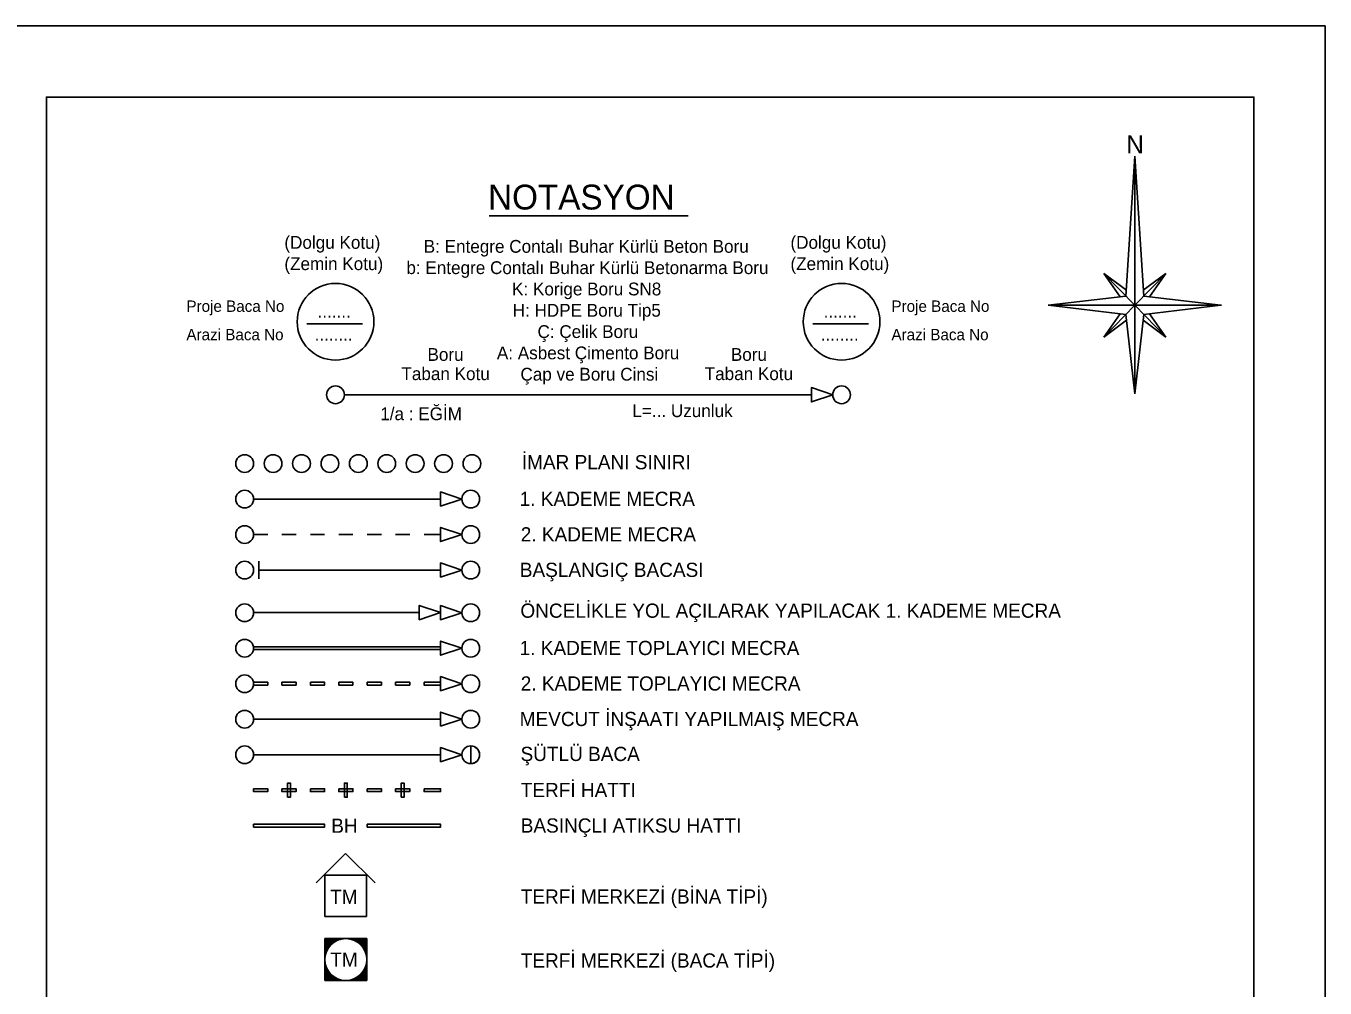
# Model space of a CAD drawing. Extents: x -10 to 1145, y -10 to 821.
# Drawn here: x 962.1 to 1145, y 685.6 to 821 of the extents above; entities that cross this region are included whole.
import ezdxf

# ---------------------------------------------------------------- set-up
doc = ezdxf.new("R2010")
doc.units = 0
for name, color, linetype in [('Default', 7, 'Continuous'), ('Lejand', 7, 'Continuous'), ('Level 51', 7, 'Continuous'), ('Level 52', 7, 'Continuous')]:
    doc.layers.add(name, color=color, linetype=linetype)

# ---------------------------------------------------------------- blocks, each defined once
blk = doc.blocks.new('OK')
at = {"layer": 'Default'}
blk.add_lwpolyline([(1.25, 0), (4.25, 1), (4.25, -1), (1.25, 0)], dxfattribs=at)
blk = doc.blocks.new('MENHOLE')
at = {"layer": 'Default'}
blk.add_circle((0, 0), 1.25, dxfattribs=at)

msp = doc.modelspace()

# ---------------------------------------------------------------- linework, layer by layer
at = {"layer": 'Lejand'}
for p, q in [((1118.22, 802.67), (1116.97, 782.96)), ((1118.22, 802.67), (1119.47, 782.96)), ((1118.22, 802.67), (1118.22, 769.23)), ((1027.33, 794.26), (1055.35, 794.26)), ((1113.84, 786.17), (1117.03, 783.81)), ((1116.17, 782.87), (1113.84, 786.17)), ((1113.84, 786.17), (1118.22, 781.68)), ((1122.6, 786.17), (1118.22, 781.68)), ((1122.6, 786.17), (1119.42, 783.81)), ((1120.27, 782.87), (1122.6, 786.17)), ((1106.03, 781.68), (1116.97, 782.96)), ((1130.35, 781.68), (1119.47, 782.96)), ((1118.22, 781.68), (1106.03, 781.68)), ((1106.03, 781.68), (1116.97, 780.4)), ((1113.84, 777.19), (1118.22, 781.68)), ((1122.6, 777.19), (1118.22, 781.68)), ((1118.22, 781.68), (1130.41, 781.68)), ((1130.35, 781.68), (1119.47, 780.4)), ((1116.17, 780.49), (1113.84, 777.19)), ((1113.84, 777.19), (1117.07, 779.58)), ((1116.97, 780.4), (1118.22, 769.23)), ((1119.47, 780.4), (1118.22, 769.23)), ((1122.6, 777.19), (1119.38, 779.58)), ((1120.27, 780.49), (1122.6, 777.19)), ((1001.65, 779.07), (1009.48, 779.07)), ((1072.9, 779.07), (1080.74, 779.07)), ((1006.94, 769.07), (1072.69, 769.08)), ((1020.48, 754.4), (994.15, 754.4)), ((996.15, 749.4), (994.15, 749.4)), ((1000.15, 749.4), (998.15, 749.4)), ((1004.15, 749.4), (1002.15, 749.4)), ((1008.15, 749.4), (1006.15, 749.4)), ((1012.15, 749.4), (1010.15, 749.4)), ((1016.15, 749.4), (1014.15, 749.4)), ((1020.48, 749.4), (1018.15, 749.4)), ((994.9, 745.64), (994.9, 743.14)), ((1020.48, 744.4), (994.9, 744.4)), ((1017.48, 738.41), (994.15, 738.41)), ((1020.48, 723.4), (994.15, 723.4)), ((1020.48, 718.4), (994.15, 718.4)), ((1007.12, 704.5), (1002.98, 700.37)), ((1007.12, 704.5), (1011.25, 700.37)), ((1010.04, 701.45), (1004.19, 701.45)), ((1004.19, 701.45), (1004.19, 695.6)), ((1010.04, 701.45), (1010.04, 695.6)), ((1010.04, 695.6), (1004.19, 695.6)), ((1004.19, 692.5), (1004.19, 686.6)), ((1010.09, 692.5), (1004.19, 692.5)), ((1006.38, 692.4), (1004.19, 692.4)), ((1006.07, 692.3), (1004.19, 692.3)), ((1005.85, 692.2), (1004.19, 692.2)), ((1005.66, 692.1), (1004.19, 692.1)), ((1005.5, 692), (1004.19, 692)), ((1005.36, 691.9), (1004.19, 691.9)), ((1005.23, 691.8), (1004.19, 691.8)), ((1005.12, 691.7), (1004.19, 691.7)), ((1005.02, 691.6), (1004.19, 691.6)), ((1004.93, 691.5), (1004.19, 691.5)), ((1004.84, 691.4), (1004.19, 691.4)), ((1004.29, 692.5), (1004.29, 690.31)), ((1004.39, 692.5), (1004.39, 690.62)), ((1004.49, 692.5), (1004.49, 690.85)), ((1004.59, 692.5), (1004.59, 691.03)), ((1004.69, 692.5), (1004.69, 691.19)), ((1004.79, 692.5), (1004.79, 691.33)), ((1004.89, 692.5), (1004.89, 691.46)), ((1004.99, 692.5), (1004.99, 691.57)), ((1005.09, 692.5), (1005.09, 691.67)), ((1005.19, 692.5), (1005.19, 691.76)), ((1005.29, 692.5), (1005.29, 691.85)), ((1005.39, 692.5), (1005.39, 691.93)), ((1005.49, 692.5), (1005.49, 692)), ((1005.59, 692.5), (1005.59, 692.06)), ((1005.69, 692.5), (1005.69, 692.12)), ((1005.79, 692.5), (1005.79, 692.17)), ((1005.89, 692.5), (1005.89, 692.22)), ((1005.99, 692.5), (1005.99, 692.27)), ((1006.09, 692.5), (1006.09, 692.31)), ((1006.19, 692.5), (1006.19, 692.34)), ((1006.29, 692.5), (1006.29, 692.38)), ((1006.39, 692.5), (1006.39, 692.4)), ((1006.49, 692.5), (1006.49, 692.43)), ((1006.59, 692.5), (1006.59, 692.45)), ((1006.69, 692.5), (1006.69, 692.47)), ((1006.79, 692.5), (1006.79, 692.48)), ((1007.39, 692.5), (1007.39, 692.49)), ((1007.49, 692.5), (1007.49, 692.48)), ((1007.59, 692.5), (1007.59, 692.47)), ((1007.69, 692.5), (1007.69, 692.45)), ((1007.79, 692.5), (1007.79, 692.43)), ((1007.89, 692.5), (1007.89, 692.4)), ((1010.09, 692.4), (1007.9, 692.4)), ((1007.99, 692.5), (1007.99, 692.38)), ((1008.09, 692.5), (1008.09, 692.34)), ((1008.19, 692.5), (1008.19, 692.31)), ((1010.09, 692.3), (1008.21, 692.3)), ((1008.29, 692.5), (1008.29, 692.27)), ((1008.39, 692.5), (1008.39, 692.22)), ((1010.09, 692.2), (1008.44, 692.2)), ((1008.49, 692.5), (1008.49, 692.17)), ((1008.59, 692.5), (1008.59, 692.12)), ((1010.09, 692.1), (1008.63, 692.1)), ((1008.69, 692.5), (1008.69, 692.06)), ((1008.79, 692.5), (1008.79, 692)), ((1010.09, 692), (1008.79, 692)), ((1008.89, 692.5), (1008.89, 691.93)), ((1010.09, 691.9), (1008.93, 691.9)), ((1008.99, 692.5), (1008.99, 691.85)), ((1010.09, 691.8), (1009.05, 691.8)), ((1009.09, 692.5), (1009.09, 691.76)), ((1010.09, 691.7), (1009.16, 691.7)), ((1009.19, 692.5), (1009.19, 691.67)), ((1010.09, 691.6), (1009.26, 691.6)), ((1009.29, 692.5), (1009.29, 691.57)), ((1010.09, 691.5), (1009.36, 691.5)), ((1009.39, 692.5), (1009.39, 691.46)), ((1010.09, 691.4), (1009.44, 691.4)), ((1009.49, 692.5), (1009.49, 691.33)), ((1009.59, 692.5), (1009.59, 691.19)), ((1009.69, 692.5), (1009.69, 691.03)), ((1009.79, 692.5), (1009.79, 690.85)), ((1009.89, 692.5), (1009.89, 690.62)), ((1009.99, 692.5), (1009.99, 690.31)), ((1010.09, 692.5), (1010.09, 686.6)), ((1004.77, 691.3), (1004.19, 691.3)), ((1004.7, 691.2), (1004.19, 691.2)), ((1004.63, 691.1), (1004.19, 691.1)), ((1004.57, 691), (1004.19, 691)), ((1004.52, 690.9), (1004.19, 690.9)), ((1004.47, 690.8), (1004.19, 690.8)), ((1004.43, 690.7), (1004.19, 690.7)), ((1004.39, 690.6), (1004.19, 690.6)), ((1004.35, 690.5), (1004.19, 690.5)), ((1004.32, 690.4), (1004.19, 690.4)), ((1004.29, 690.3), (1004.19, 690.3)), ((1004.26, 690.2), (1004.19, 690.2)), ((1004.24, 690.1), (1004.19, 690.1)), ((1004.23, 690), (1004.19, 690)), ((1004.21, 689.9), (1004.19, 689.9)), ((1004.2, 689.8), (1004.19, 689.8)), ((1010.09, 691.3), (1009.52, 691.3)), ((1010.09, 691.2), (1009.59, 691.2)), ((1010.09, 691.1), (1009.65, 691.1)), ((1010.09, 691), (1009.71, 691)), ((1010.09, 690.9), (1009.77, 690.9)), ((1010.09, 690.8), (1009.81, 690.8)), ((1010.09, 690.7), (1009.86, 690.7)), ((1010.09, 690.6), (1009.9, 690.6)), ((1010.09, 690.5), (1009.94, 690.5)), ((1010.09, 690.4), (1009.97, 690.4)), ((1010.09, 690.3), (1010, 690.3)), ((1010.09, 690.2), (1010.02, 690.2)), ((1010.09, 690.1), (1010.04, 690.1)), ((1010.09, 690), (1010.06, 690)), ((1010.09, 689.9), (1010.07, 689.9)), ((1004.2, 689.4), (1004.19, 689.4)), ((1004.21, 689.2), (1004.19, 689.2)), ((1004.23, 689.1), (1004.19, 689.1)), ((1004.24, 689), (1004.19, 689)), ((1004.26, 688.9), (1004.19, 688.9)), ((1004.29, 688.8), (1004.19, 688.8)), ((1004.32, 688.7), (1004.19, 688.7)), ((1004.35, 688.6), (1004.19, 688.6)), ((1004.39, 688.5), (1004.19, 688.5)), ((1004.43, 688.4), (1004.19, 688.4)), ((1004.47, 688.3), (1004.19, 688.3)), ((1004.52, 688.2), (1004.19, 688.2)), ((1004.57, 688.1), (1004.19, 688.1)), ((1004.63, 688), (1004.19, 688)), ((1004.7, 687.9), (1004.19, 687.9)), ((1004.77, 687.8), (1004.19, 687.8)), ((1004.84, 687.7), (1004.19, 687.7)), ((1004.29, 688.79), (1004.29, 686.6)), ((1004.39, 688.48), (1004.39, 686.6)), ((1004.49, 688.25), (1004.49, 686.6)), ((1004.59, 688.07), (1004.59, 686.6)), ((1004.69, 687.91), (1004.69, 686.6)), ((1004.79, 687.77), (1004.79, 686.6)), ((1010.09, 687.7), (1009.44, 687.7)), ((1009.49, 687.77), (1009.49, 686.6)), ((1010.09, 687.8), (1009.52, 687.8)), ((1009.59, 687.91), (1009.59, 686.6)), ((1010.09, 687.9), (1009.59, 687.9)), ((1010.09, 688), (1009.65, 688)), ((1009.69, 688.07), (1009.69, 686.6)), ((1010.09, 688.1), (1009.71, 688.1)), ((1010.09, 688.2), (1009.77, 688.2)), ((1009.79, 688.25), (1009.79, 686.6)), ((1010.09, 688.3), (1009.81, 688.3)), ((1010.09, 688.4), (1009.86, 688.4)), ((1009.89, 688.48), (1009.89, 686.6)), ((1010.09, 688.5), (1009.9, 688.5)), ((1010.09, 688.6), (1009.94, 688.6)), ((1010.09, 688.7), (1009.97, 688.7)), ((1009.99, 688.79), (1009.99, 686.6)), ((1010.09, 688.8), (1010, 688.8)), ((1010.09, 688.9), (1010.02, 688.9)), ((1010.09, 689), (1010.04, 689)), ((1010.09, 689.1), (1010.06, 689.1)), ((1010.09, 689.2), (1010.07, 689.2)), ((1010.09, 689.3), (1010.08, 689.3)), ((1004.93, 687.6), (1004.19, 687.6)), ((1005.02, 687.5), (1004.19, 687.5)), ((1005.12, 687.4), (1004.19, 687.4)), ((1005.23, 687.3), (1004.19, 687.3)), ((1005.36, 687.2), (1004.19, 687.2)), ((1005.5, 687.1), (1004.19, 687.1)), ((1005.66, 687), (1004.19, 687)), ((1005.85, 686.9), (1004.19, 686.9)), ((1006.07, 686.8), (1004.19, 686.8)), ((1006.38, 686.7), (1004.19, 686.7)), ((1010.09, 686.6), (1004.19, 686.6)), ((1004.89, 687.64), (1004.89, 686.6)), ((1004.99, 687.53), (1004.99, 686.6)), ((1005.09, 687.43), (1005.09, 686.6)), ((1005.19, 687.34), (1005.19, 686.6)), ((1005.29, 687.25), (1005.29, 686.6)), ((1005.39, 687.18), (1005.39, 686.6)), ((1005.49, 687.1), (1005.49, 686.6)), ((1005.59, 687.04), (1005.59, 686.6)), ((1005.69, 686.98), (1005.69, 686.6)), ((1005.79, 686.93), (1005.79, 686.6)), ((1005.89, 686.88), (1005.89, 686.6)), ((1005.99, 686.83), (1005.99, 686.6)), ((1006.09, 686.79), (1006.09, 686.6)), ((1006.19, 686.76), (1006.19, 686.6)), ((1006.29, 686.73), (1006.29, 686.6)), ((1006.39, 686.7), (1006.39, 686.6)), ((1006.49, 686.67), (1006.49, 686.6)), ((1006.59, 686.65), (1006.59, 686.6)), ((1006.69, 686.63), (1006.69, 686.6)), ((1006.79, 686.62), (1006.79, 686.6)), ((1007.49, 686.62), (1007.49, 686.6)), ((1007.59, 686.63), (1007.59, 686.6)), ((1007.69, 686.65), (1007.69, 686.6)), ((1007.79, 686.67), (1007.79, 686.6)), ((1007.89, 686.7), (1007.89, 686.6)), ((1010.09, 686.7), (1007.9, 686.7)), ((1007.99, 686.73), (1007.99, 686.6)), ((1008.09, 686.76), (1008.09, 686.6)), ((1008.19, 686.79), (1008.19, 686.6)), ((1010.09, 686.8), (1008.21, 686.8)), ((1008.29, 686.83), (1008.29, 686.6)), ((1008.39, 686.88), (1008.39, 686.6)), ((1010.09, 686.9), (1008.44, 686.9)), ((1008.49, 686.93), (1008.49, 686.6)), ((1008.59, 686.98), (1008.59, 686.6)), ((1010.09, 687), (1008.63, 687)), ((1008.69, 687.04), (1008.69, 686.6)), ((1008.79, 687.1), (1008.79, 686.6)), ((1010.09, 687.1), (1008.79, 687.1)), ((1008.89, 687.18), (1008.89, 686.6)), ((1010.09, 687.2), (1008.93, 687.2)), ((1008.99, 687.25), (1008.99, 686.6)), ((1010.09, 687.3), (1009.05, 687.3)), ((1009.09, 687.34), (1009.09, 686.6)), ((1010.09, 687.4), (1009.16, 687.4)), ((1009.19, 687.43), (1009.19, 686.6)), ((1010.09, 687.5), (1009.26, 687.5)), ((1009.29, 687.53), (1009.29, 686.6)), ((1010.09, 687.6), (1009.36, 687.6)), ((1009.39, 687.64), (1009.39, 686.6))]:
    msp.add_line(p, q, dxfattribs=at)
for points in [[(994.15, 733.6), (1020.48, 733.6), (1020.48, 733.2), (994.15, 733.2)], [(994.15, 728.6), (996.15, 728.6), (996.15, 728.2), (994.15, 728.2)], [(998.15, 728.6), (1000.15, 728.6), (1000.15, 728.2), (998.15, 728.2)], [(1002.15, 728.6), (1004.15, 728.6), (1004.15, 728.2), (1002.15, 728.2)], [(1006.15, 728.6), (1008.15, 728.6), (1008.15, 728.2), (1006.15, 728.2)], [(1010.15, 728.6), (1012.15, 728.6), (1012.15, 728.2), (1010.15, 728.2)], [(1014.15, 728.6), (1016.15, 728.6), (1016.15, 728.2), (1014.15, 728.2)], [(1018.15, 728.6), (1020.48, 728.6), (1020.48, 728.2), (1018.15, 728.2)], [(1020.47, 722.4), (1020.48, 724.4), (1023.48, 723.39)], [(994.15, 713.6), (996.15, 713.6), (996.15, 713.2), (994.15, 713.2)], [(998.15, 713.6), (1000.15, 713.6), (1000.15, 713.2), (998.15, 713.2)], [(998.95, 712.4), (998.95, 714.4), (999.35, 714.4), (999.35, 712.4)], [(1002.15, 713.6), (1004.15, 713.6), (1004.15, 713.2), (1002.15, 713.2)], [(1006.15, 713.6), (1008.15, 713.6), (1008.15, 713.2), (1006.15, 713.2)], [(1006.95, 712.4), (1006.95, 714.4), (1007.35, 714.4), (1007.35, 712.4)], [(1010.15, 713.6), (1012.15, 713.6), (1012.15, 713.2), (1010.15, 713.2)], [(1014.15, 713.6), (1016.15, 713.6), (1016.15, 713.2), (1014.15, 713.2)], [(1014.95, 712.4), (1014.95, 714.4), (1015.35, 714.4), (1015.35, 712.4)], [(1018.15, 713.6), (1020.48, 713.6), (1020.48, 713.2), (1018.15, 713.2)], [(994.15, 708.6), (1004.15, 708.6), (1004.15, 708.2), (994.15, 708.2)], [(1010.15, 708.6), (1020.48, 708.6), (1020.48, 708.2), (1010.15, 708.2)]]:
    msp.add_lwpolyline(points, close=True, dxfattribs=at)
msp.add_lwpolyline([(1024.73, 717.14), (1024.97, 717.16), (1025.21, 717.23), (1025.42, 717.35), (1025.61, 717.51), (1025.77, 717.7), (1025.88, 717.91), (1025.95, 718.15), (1025.98, 718.39), (1025.95, 718.63), (1025.88, 718.87), (1025.77, 719.08), (1025.61, 719.27), (1025.42, 719.43), (1025.21, 719.54), (1024.97, 719.62), (1024.73, 719.64), (1024.73, 717.14)], dxfattribs=at)
for centre, radius in [((1005.69, 779.36), 5.4), ((1076.94, 779.36), 5.4), ((992.9, 759.39), 1.25), ((996.9, 759.39), 1.25), ((1000.9, 759.39), 1.25), ((1004.9, 759.39), 1.25), ((1008.9, 759.39), 1.25), ((1012.9, 759.39), 1.25), ((1016.9, 759.39), 1.25), ((1020.9, 759.39), 1.25), ((1024.9, 759.39), 1.25), ((992.9, 723.39), 1.25), ((1024.73, 723.39), 1.25), ((1007.14, 689.55), 2.95)]:
    msp.add_circle(centre, radius, dxfattribs=at)
at = {"layer": 'Level 51'}
msp.add_lwpolyline([(-10, -10), (1145, -10), (1145, 821), (-10, 821)], close=True, dxfattribs=at)
at = {"layer": 'Level 52'}
msp.add_lwpolyline([(965, 287), (1135, 287), (1135, 811), (965, 811)], close=True, dxfattribs=at)

# ---------------------------------------------------------------- block references
at = {"layer": 'Lejand'}
for name, p, xscale, yscale, rotation in [('MENHOLE', (1005.69, 769.07), 1.0000122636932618, 1.0000122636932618, 0.0008205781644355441), ('OK', (1076.94, 769.07), 1.000012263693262, 1.0000122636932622, 179.87420678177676), ('MENHOLE', (1076.94, 769.07), 1.0000122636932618, 1.0000122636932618, 0.0008205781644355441), ('MENHOLE', (992.9, 754.39), 1.0000122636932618, 1.0000122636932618, 0.0008205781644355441), ('OK', (1024.73, 754.39), 1.000012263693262, 1.0000122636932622, 179.87420678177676), ('MENHOLE', (1024.73, 754.39), 1.0000122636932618, 1.0000122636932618, 0.0008205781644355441), ('MENHOLE', (992.9, 749.39), 1.0000122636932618, 1.0000122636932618, 0.0008205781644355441), ('OK', (1024.73, 749.39), 1.000012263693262, 1.0000122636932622, 179.87420678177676), ('MENHOLE', (1024.73, 749.39), 1.0000122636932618, 1.0000122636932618, 0.0008205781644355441), ('MENHOLE', (992.9, 744.39), 1.0000122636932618, 1.0000122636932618, 0.0008205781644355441), ('OK', (1024.73, 744.39), 1.000012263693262, 1.0000122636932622, 179.87420678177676), ('MENHOLE', (1024.73, 744.39), 1.0000122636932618, 1.0000122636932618, 0.0008205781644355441), ('MENHOLE', (992.9, 738.39), 1.0000122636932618, 1.0000122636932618, 0.0008205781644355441), ('OK', (1021.73, 738.4), 1.000012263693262, 1.0000122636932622, 179.87420678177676), ('OK', (1024.73, 738.39), 1.000012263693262, 1.0000122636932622, 179.87420678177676), ('MENHOLE', (1024.73, 738.39), 1.0000122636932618, 1.0000122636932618, 0.0008205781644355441), ('MENHOLE', (992.9, 733.39), 1.0000122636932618, 1.0000122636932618, 0.0008205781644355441), ('OK', (1024.73, 733.39), 1.000012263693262, 1.0000122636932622, 179.87420678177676), ('MENHOLE', (1024.73, 733.39), 1.0000122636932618, 1.0000122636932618, 0.0008205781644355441), ('MENHOLE', (992.9, 728.39), 1.0000122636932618, 1.0000122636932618, 0.0008205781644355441), ('OK', (1024.73, 728.39), 1.000012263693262, 1.0000122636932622, 179.87420678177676), ('MENHOLE', (1024.73, 728.39), 1.0000122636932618, 1.0000122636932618, 0.0008205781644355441), ('MENHOLE', (992.9, 718.39), 1.0000122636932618, 1.0000122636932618, 0.0008205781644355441), ('OK', (1024.73, 718.39), 1.000012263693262, 1.0000122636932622, 179.87420678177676), ('MENHOLE', (1024.73, 718.39), 1.0000122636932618, 1.0000122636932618, 0.0008205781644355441)]:
    msp.add_blockref(name, p, dxfattribs=dict(at, xscale=xscale, yscale=yscale, rotation=rotation))

# ---------------------------------------------------------------- texts
msp.add_text('N', height=2.56, dxfattribs=at).set_placement((1117.02, 803.06))
for s, height, p in [('NOTASYON', 3.5, (1027.17, 795.16)), ('(Dolgu Kotu)', 1.8, (998.49, 789.63)), ('B: Entegre Contalı Buhar Kürlü Beton Boru', 1.8, (1018.11, 789.07)), ('(Dolgu Kotu)', 1.8, (1069.74, 789.63)), ('(Zemin Kotu)', 1.8, (998.49, 786.63)), ('(Zemin Kotu)', 1.8, (1069.74, 786.63)), ('b: Entegre Contalı Buhar Kürlü Betonarma Boru', 1.8, (1015.67, 786.07)), ('K: Korige Boru SN8', 1.8, (1030.55, 783.07)), ('Proje Baca No', 1.6, (984.7, 780.75)), ('H: HDPE Boru Tip5', 1.8, (1030.63, 780.07)), ('Proje Baca No', 1.6, (1083.96, 780.75)), ('.......', 1.8, (1003.16, 779.94)), ('.......', 1.8, (1074.41, 779.94)), ('Arazi Baca No', 1.6, (984.7, 776.75)), ('Ç: Çelik Boru', 1.8, (1034.13, 777.07)), ('Arazi Baca No', 1.6, (1083.96, 776.75)), ('........', 1.8, (1002.75, 776.7)), ('Boru', 1.8, (1018.64, 773.85)), ('A: Asbest Çimento Boru', 1.8, (1028.41, 774.07)), ('Boru', 1.8, (1061.35, 773.85)), ('........', 1.8, (1074, 776.7)), ('Taban Kotu', 1.8, (1014.97, 771.14)), ('Çap ve Boru Cinsi', 1.8, (1031.73, 771.07)), ('Taban Kotu', 1.8, (1057.67, 771.14)), ('1/a : EĞİM', 1.8, (1011.99, 765.5)), ('L=... Uzunluk', 1.8, (1047.49, 765.93)), ('İMAR PLANI SINIRI', 2, (1031.92, 758.59)), ('1. KADEME MECRA', 2, (1031.62, 753.43)), ('2. KADEME MECRA', 2, (1031.77, 748.43)), ('BAŞLANGIÇ BACASI', 2, (1031.64, 743.43)), ('ÖNCELİKLE YOL AÇILARAK YAPILACAK 1. KADEME MECRA', 2, (1031.72, 737.68)), ('1. KADEME TOPLAYICI MECRA', 2, (1031.62, 732.43)), ('2. KADEME TOPLAYICI MECRA', 2, (1031.77, 727.43)), ('MEVCUT İNŞAATI YAPILMAIŞ MECRA', 2, (1031.62, 722.43)), ('ŞÜTLÜ BACA', 2, (1031.74, 717.51)), ('TERFİ HATTI', 2, (1031.77, 712.43)), ('BH', 2, (1005.09, 707.4)), ('BASINÇLI ATIKSU HATTI', 2, (1031.77, 707.43)), ('TM', 2, (1004.93, 697.4)), ('TERFİ MERKEZİ (BİNA TİPİ)', 2, (1031.77, 697.43)), ('TM', 2, (1004.96, 688.55)), ('TERFİ MERKEZİ (BACA TİPİ)', 2, (1031.77, 688.43))]:
    msp.add_text(s, height=height, rotation=0.0008, dxfattribs=at).set_placement(p)

doc.saveas('drawing.dxf')
